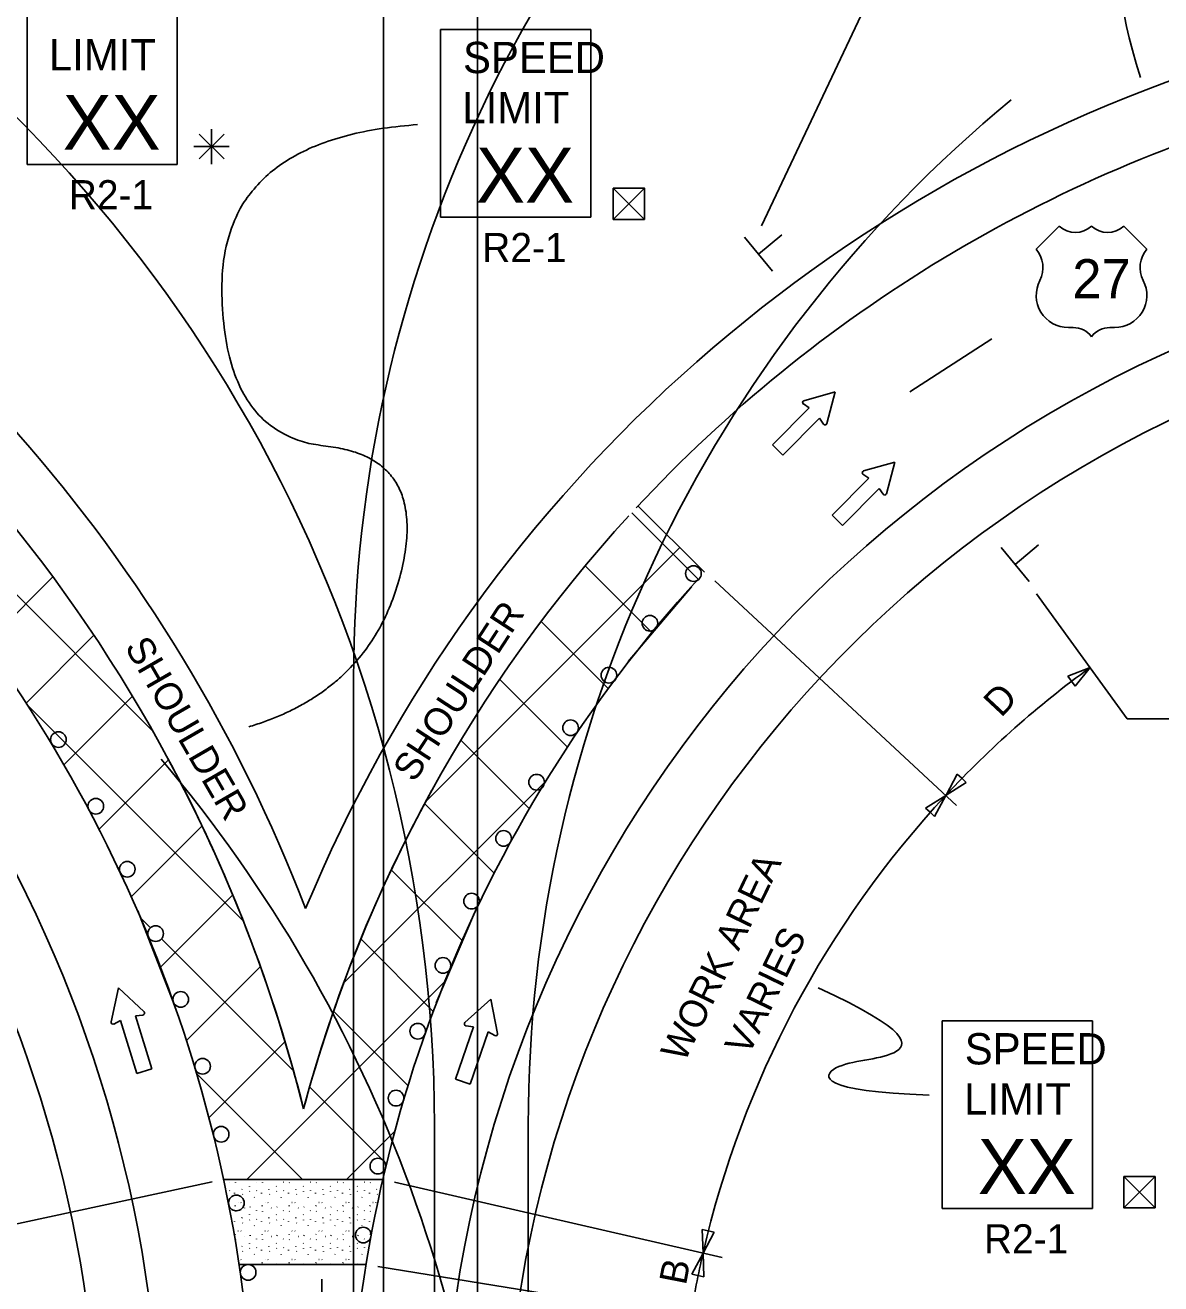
# Model space of a CAD drawing. Extents: x 16728 to 19508, y 5553 to 7079.
# Drawn here: x 16889.1 to 17179.3, y 6484.5 to 6806.3 of the extents above; entities that cross this region are included whole.
import ezdxf

# ---------------------------------------------------------------- set-up
doc = ezdxf.new("R2010")
doc.units = 0
for name, color, linetype in [('ALI_LEGAL_EX', 7, 'Continuous'), ('MT_SCRATCH_LEVEL_A', 7, 'Continuous'), ('MT_SCRATCH_LEVEL_E', 7, 'Continuous'), ('PAVT_EDGE_EX', 7, 'Continuous'), ('TRAFFIC_SIGNS_PR', 7, 'Continuous'), ('TYPICAL_EX', 7, 'Continuous'), ('TYPICAL_TEXT_DIMEN_PR', 7, 'Continuous')]:
    doc.layers.add(name, color=color, linetype=linetype)

msp = doc.modelspace()

# ---------------------------------------------------------------- linework, layer by layer
at = {"layer": 'ALI_LEGAL_EX'}
for p, q in [((16980.68, 6974.12), (16980.68, 6155.98)), ((17004.68, 6974.12), (17004.68, 6155.98)), ((16980.68, 6877.04), (16980.68, 6013.12)), ((17004.68, 6877.04), (17004.68, 6013.12)), ((16973.01, 6139.03), (16973.01, 6639.38)), ((16993.65, 6024.8), (16993.65, 6525.15)), ((17017.65, 6024.8), (17017.65, 6525.15))]:
    msp.add_line(p, q, dxfattribs=at)
for points in [[(17115.18, 6712.56), (17136.15, 6726.16)], [(17043.22, 6643.6), (17059.35, 6662.7)], [(16926.92, 6556.59), (16917.84, 6579.89)], [(16994.08, 6556.37), (17003.86, 6579.38)]]:
    msp.add_lwpolyline(points, dxfattribs=at)
for centre, radius, start, end in [((17313.01, 6639.38), 340, 129.5666, 180), ((16629.65, 6525.15), 364, 0, 57.2958), ((17357.65, 6525.15), 340, 129.5666, 180), ((16583.82, 6435.06), 364, 0, 40.1909), ((17311.82, 6435.06), 340, 137.516, 180), ((16645.75, 6383.76), 364, 0, 40.1909)]:
    msp.add_arc(centre, radius, start, end, dxfattribs=at)
at = {"layer": 'MT_SCRATCH_LEVEL_A'}
for p, q in [((17061.07, 6664.68), (17044.08, 6681.66)), ((17062.67, 6666.45), (17045.68, 6683.43)), ((16921.62, 6625.93), (16870.81, 6676.74)), ((16991.45, 6607.86), (17056.26, 6672.67)), ((17049.24, 6651.05), (17032.19, 6668.09)), ((16878.96, 6648.1), (16896.13, 6665.28)), ((17038.09, 6636.74), (17020.94, 6653.89)), ((16889.3, 6632.99), (16906.63, 6650.32)), ((17027.64, 6621.73), (17010.34, 6639.03)), ((16944.81, 6577.29), (16889.65, 6632.44)), ((16898.97, 6617.2), (16916.49, 6634.73)), ((17017.92, 6606), (17000.4, 6623.52)), ((16907.94, 6600.72), (16925.71, 6618.49)), ((16970.45, 6561.4), (17022.19, 6613.14)), ((17008.93, 6589.53), (16991.15, 6607.31)), ((16916.17, 6583.5), (16934.26, 6601.59)), ((17000.73, 6572.27), (16982.62, 6590.39)), ((16923.64, 6565.51), (16942.1, 6583.97)), ((16921.08, 6575.56), (16918.53, 6578.11)), ((16957.63, 6539.01), (16923.9, 6572.73)), ((16993.37, 6554.18), (16974.85, 6572.7)), ((16930.28, 6546.69), (16949.19, 6565.61)), ((16945.7, 6511.2), (16996.34, 6561.84)), ((16986.9, 6535.2), (16967.87, 6554.22)), ((16936.02, 6526.98), (16955.48, 6546.44)), ((16959.98, 6511.2), (16932.86, 6538.32)), ((16981.44, 6515.19), (16961.77, 6534.87)), ((16971.15, 6511.2), (16983.54, 6523.59)), ((16939.76, 6511.2), (16980.45, 6511.2)), ((16939.76, 6511.2), (16980.45, 6511.2)), ((16980.45, 6511.2), (16939.76, 6511.2)), ((16941.26, 6510.55), (16941.31, 6510.47)), ((16942.79, 6510.41), (16942.84, 6510.33)), ((16945.1, 6511.2), (16945.13, 6511.15)), ((16948.15, 6510.55), (16948.2, 6510.47)), ((16949.68, 6510.41), (16949.73, 6510.33)), ((16951.99, 6511.2), (16952.02, 6511.15)), ((16955.04, 6510.55), (16955.09, 6510.47)), ((16956.57, 6510.41), (16956.62, 6510.33)), ((16958.88, 6511.2), (16958.91, 6511.15)), ((16961.92, 6510.55), (16961.97, 6510.47)), ((16963.45, 6510.41), (16963.51, 6510.33)), ((16965.76, 6511.2), (16965.8, 6511.15)), ((16968.81, 6510.55), (16968.86, 6510.47)), ((16970.34, 6510.41), (16970.39, 6510.33)), ((16972.65, 6511.2), (16972.68, 6511.15)), ((16975.7, 6510.55), (16975.75, 6510.47)), ((16977.23, 6510.41), (16977.28, 6510.33)), ((16979.54, 6511.2), (16979.57, 6511.15)), ((16940.69, 6506.59), (16940.74, 6506.71)), ((16941.31, 6508.34), (16941.36, 6508.27)), ((16942.59, 6507.77), (16942.6, 6507.65)), ((16944.43, 6508.62), (16944.48, 6508.74)), ((16944.62, 6507.42), (16944.67, 6507.35)), ((16946.36, 6509.49), (16946.41, 6509.41)), ((16946.4, 6508.09), (16946.45, 6508.21)), ((16947.58, 6506.59), (16947.63, 6506.71)), ((16948.2, 6508.34), (16948.25, 6508.27)), ((16949.48, 6507.77), (16949.49, 6507.65)), ((16951.32, 6508.62), (16951.37, 6508.74)), ((16951.51, 6507.42), (16951.56, 6507.35)), ((16953.25, 6509.49), (16953.3, 6509.41)), ((16953.29, 6508.09), (16953.34, 6508.21)), ((16954.47, 6506.59), (16954.52, 6506.71)), ((16955.08, 6508.34), (16955.14, 6508.27)), ((16956.37, 6507.77), (16956.38, 6507.65)), ((16958.21, 6508.62), (16958.26, 6508.74)), ((16958.4, 6507.42), (16958.45, 6507.35)), ((16960.13, 6509.49), (16960.19, 6509.41)), ((16960.18, 6508.09), (16960.23, 6508.21)), ((16961.35, 6506.59), (16961.41, 6506.71)), ((16961.97, 6508.34), (16962.02, 6508.27)), ((16963.25, 6507.77), (16963.27, 6507.65)), ((16965.1, 6508.62), (16965.15, 6508.74)), ((16965.28, 6507.42), (16965.33, 6507.35)), ((16967.02, 6509.49), (16967.07, 6509.41)), ((16967.06, 6508.09), (16967.12, 6508.21)), ((16968.24, 6506.59), (16968.29, 6506.71)), ((16968.86, 6508.34), (16968.91, 6508.27)), ((16970.14, 6507.77), (16970.15, 6507.65)), ((16971.98, 6508.62), (16972.03, 6508.74)), ((16972.17, 6507.42), (16972.22, 6507.35)), ((16973.91, 6509.49), (16973.96, 6509.41)), ((16973.95, 6508.09), (16974, 6508.21)), ((16975.13, 6506.59), (16975.18, 6506.71)), ((16975.75, 6508.34), (16975.8, 6508.27)), ((16977.03, 6507.77), (16977.04, 6507.65)), ((16978.87, 6508.62), (16978.92, 6508.74)), ((16979.06, 6507.42), (16979.11, 6507.35)), ((16942.71, 6504.39), (16942.76, 6504.51)), ((16943.47, 6505.35), (16943.53, 6505.28)), ((16944.21, 6505.32), (16944.26, 6505.25)), ((16945.08, 6503.94), (16945.13, 6503.87)), ((16946.53, 6504.1), (16946.58, 6504.21)), ((16949.6, 6504.39), (16949.65, 6504.51)), ((16950.36, 6505.35), (16950.41, 6505.28)), ((16951.1, 6505.32), (16951.15, 6505.25)), ((16951.97, 6503.94), (16952.02, 6503.87)), ((16953.42, 6504.1), (16953.47, 6504.21)), ((16956.49, 6504.39), (16956.54, 6504.51)), ((16957.25, 6505.35), (16957.3, 6505.28)), ((16957.99, 6505.32), (16958.04, 6505.25)), ((16958.86, 6503.94), (16958.91, 6503.87)), ((16960.31, 6504.1), (16960.36, 6504.21)), ((16963.37, 6504.39), (16963.42, 6504.51)), ((16964.14, 6505.35), (16964.19, 6505.28)), ((16964.88, 6505.32), (16964.93, 6505.25)), ((16965.74, 6503.94), (16965.8, 6503.87)), ((16967.19, 6504.1), (16967.24, 6504.21)), ((16970.26, 6504.39), (16970.31, 6504.51)), ((16971.03, 6505.35), (16971.08, 6505.28)), ((16971.76, 6505.32), (16971.81, 6505.25)), ((16972.63, 6503.94), (16972.68, 6503.87)), ((16974.08, 6504.1), (16974.13, 6504.21)), ((16977.15, 6504.39), (16977.2, 6504.51)), ((16977.91, 6505.35), (16977.96, 6505.28)), ((16978.65, 6505.32), (16978.7, 6505.25)), ((16942.59, 6500.48), (16942.6, 6500.37)), ((16942.79, 6503.13), (16942.84, 6503.05)), ((16944.43, 6501.34), (16944.48, 6501.45)), ((16946.36, 6502.21), (16946.41, 6502.13)), ((16946.4, 6500.81), (16946.45, 6500.92)), ((16948.15, 6503.27), (16948.2, 6503.19)), ((16948.2, 6501.06), (16948.25, 6500.98)), ((16949.48, 6500.48), (16949.49, 6500.37)), ((16949.68, 6503.13), (16949.73, 6503.05)), ((16951.32, 6501.34), (16951.37, 6501.45)), ((16953.25, 6502.21), (16953.3, 6502.13)), ((16953.29, 6500.81), (16953.34, 6500.92)), ((16955.04, 6503.27), (16955.09, 6503.19)), ((16955.08, 6501.06), (16955.14, 6500.98)), ((16956.37, 6500.48), (16956.38, 6500.37)), ((16956.57, 6503.13), (16956.62, 6503.05)), ((16958.21, 6501.34), (16958.26, 6501.45)), ((16960.13, 6502.21), (16960.19, 6502.13)), ((16960.18, 6500.81), (16960.23, 6500.92)), ((16961.92, 6503.27), (16961.97, 6503.19)), ((16961.97, 6501.06), (16962.02, 6500.98)), ((16963.25, 6500.48), (16963.27, 6500.37)), ((16963.45, 6503.13), (16963.51, 6503.05)), ((16965.1, 6501.34), (16965.15, 6501.45)), ((16967.02, 6502.21), (16967.07, 6502.13)), ((16967.06, 6500.81), (16967.12, 6500.92)), ((16968.81, 6503.27), (16968.86, 6503.19)), ((16968.86, 6501.06), (16968.91, 6500.98)), ((16970.14, 6500.48), (16970.15, 6500.37)), ((16970.34, 6503.13), (16970.39, 6503.05)), ((16971.98, 6501.34), (16972.03, 6501.45)), ((16973.91, 6502.21), (16973.96, 6502.13)), ((16973.95, 6500.81), (16974, 6500.92)), ((16975.7, 6503.27), (16975.75, 6503.19)), ((16975.75, 6501.06), (16975.8, 6500.98)), ((16977.03, 6500.48), (16977.04, 6500.37)), ((16977.23, 6503.13), (16977.28, 6503.05)), ((16942.71, 6497.11), (16942.76, 6497.23)), ((16943.47, 6498.07), (16943.53, 6497.99)), ((16944.21, 6498.04), (16944.26, 6497.96)), ((16944.62, 6500.14), (16944.67, 6500.06)), ((16947.58, 6499.31), (16947.63, 6499.42)), ((16949.6, 6497.11), (16949.65, 6497.23)), ((16950.36, 6498.07), (16950.41, 6497.99)), ((16951.1, 6498.04), (16951.15, 6497.96)), ((16951.51, 6500.14), (16951.56, 6500.06)), ((16954.47, 6499.31), (16954.52, 6499.42)), ((16956.49, 6497.11), (16956.54, 6497.23)), ((16957.25, 6498.07), (16957.3, 6497.99)), ((16957.99, 6498.04), (16958.04, 6497.96)), ((16958.4, 6500.14), (16958.45, 6500.06)), ((16961.35, 6499.31), (16961.41, 6499.42)), ((16963.37, 6497.11), (16963.42, 6497.23)), ((16964.14, 6498.07), (16964.19, 6497.99)), ((16964.88, 6498.04), (16964.93, 6497.96)), ((16965.28, 6500.14), (16965.33, 6500.06)), ((16968.24, 6499.31), (16968.29, 6499.42)), ((16970.26, 6497.11), (16970.31, 6497.23)), ((16971.03, 6498.07), (16971.08, 6497.99)), ((16971.76, 6498.04), (16971.81, 6497.96)), ((16972.17, 6500.14), (16972.22, 6500.06)), ((16975.13, 6499.31), (16975.18, 6499.42)), ((16977.15, 6497.11), (16977.2, 6497.23)), ((16942.79, 6495.84), (16942.84, 6495.77)), ((16944.43, 6494.05), (16944.48, 6494.17)), ((16945.08, 6496.66), (16945.13, 6496.58)), ((16946.36, 6494.92), (16946.41, 6494.85)), ((16946.53, 6496.81), (16946.58, 6496.93)), ((16948.15, 6495.98), (16948.2, 6495.9)), ((16949.68, 6495.84), (16949.73, 6495.77)), ((16951.32, 6494.05), (16951.37, 6494.17)), ((16951.97, 6496.66), (16952.02, 6496.58)), ((16953.25, 6494.92), (16953.3, 6494.85)), ((16953.42, 6496.81), (16953.47, 6496.93)), ((16955.04, 6495.98), (16955.09, 6495.9)), ((16956.57, 6495.84), (16956.62, 6495.77)), ((16958.21, 6494.05), (16958.26, 6494.17)), ((16958.86, 6496.66), (16958.91, 6496.58)), ((16960.13, 6494.92), (16960.19, 6494.85)), ((16960.31, 6496.81), (16960.36, 6496.93)), ((16961.92, 6495.98), (16961.97, 6495.9)), ((16963.45, 6495.84), (16963.51, 6495.77)), ((16965.1, 6494.05), (16965.15, 6494.17)), ((16965.74, 6496.66), (16965.8, 6496.58)), ((16967.02, 6494.92), (16967.07, 6494.85)), ((16967.19, 6496.81), (16967.24, 6496.93)), ((16968.81, 6495.98), (16968.86, 6495.9)), ((16970.34, 6495.84), (16970.39, 6495.77)), ((16971.98, 6494.05), (16972.03, 6494.17)), ((16972.63, 6496.66), (16972.68, 6496.58)), ((16973.91, 6494.92), (16973.96, 6494.85)), ((16974.08, 6496.81), (16974.13, 6496.93)), ((16975.7, 6495.98), (16975.75, 6495.9)), ((16977.23, 6495.84), (16977.28, 6495.77)), ((16943.53, 6490.71), (16943.53, 6490.71)), ((16944.21, 6490.75), (16944.26, 6490.68)), ((16944.62, 6492.85), (16944.67, 6492.78)), ((16946.4, 6493.52), (16946.45, 6493.64)), ((16947.58, 6492.02), (16947.63, 6492.14)), ((16948.2, 6493.77), (16948.25, 6493.7)), ((16949.48, 6493.2), (16949.49, 6493.08)), ((16950.36, 6490.78), (16950.41, 6490.71)), ((16951.1, 6490.75), (16951.15, 6490.68)), ((16951.51, 6492.85), (16951.56, 6492.78)), ((16953.29, 6493.52), (16953.34, 6493.64)), ((16954.47, 6492.02), (16954.52, 6492.14)), ((16955.08, 6493.77), (16955.14, 6493.7)), ((16956.37, 6493.2), (16956.38, 6493.08)), ((16957.25, 6490.78), (16957.3, 6490.71)), ((16957.99, 6490.75), (16958.04, 6490.68)), ((16958.4, 6492.85), (16958.45, 6492.78)), ((16960.18, 6493.52), (16960.23, 6493.64)), ((16961.35, 6492.02), (16961.41, 6492.14)), ((16961.97, 6493.77), (16962.02, 6493.7)), ((16963.25, 6493.2), (16963.27, 6493.08)), ((16964.14, 6490.78), (16964.19, 6490.71)), ((16964.88, 6490.75), (16964.93, 6490.68)), ((16965.28, 6492.85), (16965.33, 6492.78)), ((16967.06, 6493.52), (16967.12, 6493.64)), ((16968.24, 6492.02), (16968.29, 6492.14)), ((16968.86, 6493.77), (16968.91, 6493.7)), ((16970.14, 6493.2), (16970.15, 6493.08)), ((16971.03, 6490.78), (16971.08, 6490.71)), ((16971.76, 6490.75), (16971.81, 6490.68)), ((16972.17, 6492.85), (16972.22, 6492.78)), ((16973.95, 6493.52), (16974, 6493.64)), ((16975.13, 6492.02), (16975.18, 6492.14)), ((16975.75, 6493.77), (16975.8, 6493.7)), ((16943.73, 6489.46), (16976.2, 6489.46)), ((16943.73, 6489.46), (16976.2, 6489.46)), ((16946.53, 6489.53), (16946.58, 6489.64)), ((16949.6, 6489.82), (16949.65, 6489.94)), ((16953.42, 6489.53), (16953.47, 6489.64)), ((16956.49, 6489.82), (16956.54, 6489.94)), ((16960.31, 6489.53), (16960.36, 6489.64)), ((16963.37, 6489.82), (16963.42, 6489.94)), ((16967.19, 6489.53), (16967.24, 6489.64)), ((16970.26, 6489.82), (16970.31, 6489.94)), ((16974.08, 6489.53), (16974.13, 6489.64))]:
    msp.add_line(p, q, dxfattribs=at)
for centre, radius, start, end in [((16583.82, 6435.06), 388, 14.0483, 28.2673), ((16583.82, 6435.06), 388, 14.0483, 28.2673), ((17311.82, 6435.06), 364, 151.1372, 165.0045), ((17311.82, 6435.06), 364, 151.1372, 165.0044)]:
    msp.add_arc(centre, radius, start, end, dxfattribs=at)
at = {"layer": 'MT_SCRATCH_LEVEL_E'}
for p, q in [((17087.96, 6709.47), (17089.44, 6708.44)), ((17096.12, 6712.53), (17088.1, 6710.29)), ((17093.96, 6704.47), (17096.12, 6712.53)), ((17089.44, 6708.44), (17080.1, 6699.04)), ((17082.75, 6696.4), (17092.1, 6705.8)), ((17092.1, 6705.8), (17093.14, 6704.32)), ((17080.1, 6699.04), (17082.75, 6696.4)), ((17111.35, 6694.57), (17103.33, 6692.34)), ((17109.19, 6686.52), (17111.35, 6694.57)), ((17104.67, 6690.48), (17095.33, 6681.08)), ((17103.19, 6691.51), (17104.67, 6690.48)), ((17097.98, 6678.44), (17107.33, 6687.84)), ((17107.33, 6687.84), (17108.37, 6686.37)), ((17095.33, 6681.08), (17097.98, 6678.44))]:
    msp.add_line(p, q, dxfattribs=at)
for centre, start, end in [((17088.23, 6709.84), 105.5821, 235.121), ((17093.51, 6704.6), 215.1934, 344.9303), ((17103.46, 6691.89), 105.5821, 235.121), ((17108.74, 6686.64), 215.1934, 344.9303)]:
    msp.add_arc(centre, 0.463, start, end, dxfattribs=at)
at = {"layer": 'PAVT_EDGE_EX'}
for centre, radius, start, end in [((17311.82, 6435.06), 380, 105.2177, 157.5011), ((16583.82, 6435.06), 404, 21.0961, 61.4862), ((17311.82, 6435.06), 364, 105.2176, 137.0843), ((16583.82, 6435.06), 388, 14.0482, 61.4862), ((17311.82, 6435.06), 316, 105.2177, 180), ((16583.82, 6435.06), 340, 0, 61.4862), ((17311.82, 6435.06), 300, 105.2177, 180), ((16583.82, 6435.06), 324, 0, 61.4862), ((17311.82, 6435.06), 364, 137.516, 165.0045)]:
    msp.add_arc(centre, radius, start, end, dxfattribs=at)
at = {"layer": 'TRAFFIC_SIGNS_PR'}
for p, q in [((16889.53, 6770.69), (16889.53, 6818.69)), ((16927.92, 6770.69), (16927.92, 6818.69)), ((16995.2, 6805.19), (17033.6, 6805.19)), ((16995.2, 6757.19), (16995.2, 6805.19)), ((17033.6, 6757.19), (17033.6, 6805.19)), ((16889.53, 6770.69), (16927.92, 6770.69)), ((16995.2, 6757.19), (17033.6, 6757.19)), ((17123.44, 6551.75), (17161.84, 6551.75)), ((17123.44, 6503.75), (17123.44, 6551.75)), ((17161.84, 6503.75), (17161.84, 6551.75)), ((17123.44, 6503.75), (17161.84, 6503.75))]:
    msp.add_line(p, q, dxfattribs=at)
for centre in [(17059.87, 6666.11), (17048.74, 6653.41), (17038.25, 6640.13), (17028.46, 6626.68), (16897.56, 6623.67), (17019.79, 6612.77), (16907.11, 6606.63), (17011.34, 6598.39), (16915.15, 6590.52), (17003.16, 6582.36), (16922.4, 6574.05), (16995.84, 6565.92), (16928.82, 6557.24), (16989.4, 6549.11), (16934.41, 6540.13), (16983.84, 6531.99), (16939.15, 6522.76), (16979.2, 6514.61), (16943.03, 6505.19), (16975.47, 6497), (16946.05, 6487.45), (16946.05, 6487.45), (16946.05, 6487.45)]:
    msp.add_circle(centre, 2, dxfattribs=at)
at = {"layer": 'TYPICAL_EX'}
for p, q in [((17147.46, 6749.07), (17153.35, 6754.96)), ((17175.76, 6749.07), (17169.86, 6754.96)), ((17155.7, 6729.01), (17156.88, 6729.01)), ((17167.51, 6729.01), (17166.33, 6729.01))]:
    msp.add_line(p, q, dxfattribs=at)
for centre, radius, start, end in [((17157.48, 6759.26), 5.96, 226.1404, 313.8596), ((17165.73, 6759.26), 5.96, 226.1404, 313.8596), ((17141.87, 6744.35), 7.31, 333.0977, 40.1936), ((17181.34, 6744.35), 7.31, 139.8064, 206.9023), ((17155.72, 6737.25), 8.24, 152.6698, 269.9013), ((17167.5, 6737.25), 8.24, 270.0987, 27.3302), ((17156.9, 6723.1), 5.91, 37.1038, 90.1385), ((17166.32, 6723.1), 5.91, 89.8615, 142.8962)]:
    msp.add_arc(centre, radius, start, end, dxfattribs=at)
at = {"layer": 'TYPICAL_TEXT_DIMEN_PR'}
for p, q in [((17077.28, 6754.99), (17105.34, 6814.46)), ((16939.9, 6778.49), (16933.52, 6772.11)), ((16933.53, 6778.49), (16939.9, 6772.11)), ((16936.71, 6775.3), (16936.71, 6779.76)), ((16936.71, 6775.3), (16932.18, 6775.3)), ((16936.71, 6775.3), (16939.9, 6775.3)), ((16936.71, 6775.3), (16941.19, 6775.3)), ((16936.71, 6775.3), (16936.71, 6770.8)), ((17039.35, 6756.67), (17047.35, 6764.67)), ((17039.35, 6764.66), (17047.35, 6756.67)), ((17080.08, 6743.43), (17072.89, 6752.08)), ((17076.48, 6747.76), (17082.47, 6752.73)), ((17145.69, 6664.12), (17138.51, 6672.77)), ((17142.1, 6668.44), (17148.09, 6673.42)), ((17127.11, 6606.79), (17065.3, 6664.26)), ((17170.75, 6628.99), (17147.51, 6660.94)), ((17155.56, 6639.9), (17161.22, 6642.08)), ((17161.22, 6642.08), (17157.41, 6637.36)), ((17156.48, 6638.63), (17155.56, 6639.9)), ((17157.41, 6637.36), (17156.48, 6638.63)), ((17170.75, 6628.99), (17189.02, 6628.99)), ((17124.44, 6609.48), (17127.28, 6614.84)), ((17127.28, 6614.84), (17128.43, 6613.77)), ((17128.43, 6613.77), (17129.58, 6612.7)), ((17129.58, 6612.7), (17124.44, 6609.48)), ((17119.19, 6606.15), (17124.33, 6609.37)), ((17124.33, 6609.37), (17121.49, 6604.01)), ((17120.34, 6605.08), (17119.19, 6606.15)), ((17121.49, 6604.01), (17120.34, 6605.08)), ((16912.94, 6560.16), (16911.03, 6551.49)), ((16919.44, 6554.09), (16912.94, 6560.16)), ((17008.1, 6557.26), (17001.45, 6551.37)), ((17009.79, 6548.52), (17008.1, 6557.26)), ((16911.74, 6550.94), (16913.45, 6551.82)), ((16913.45, 6551.82), (16917.63, 6538.31)), ((16917.26, 6553), (16919.17, 6553.24)), ((16921.44, 6539.49), (16917.26, 6553)), ((17003.61, 6550.22), (16999.03, 6536.84)), ((17001.7, 6550.52), (17003.61, 6550.22)), ((17002.81, 6535.55), (17007.38, 6548.93)), ((17007.38, 6548.93), (17009.07, 6548)), ((16917.63, 6538.31), (16921.44, 6539.49)), ((16999.03, 6536.84), (17002.81, 6535.55)), ((16852.73, 6492.58), (16936.83, 6510.57)), ((17067.19, 6491.27), (16983.42, 6510.52)), ((17169.85, 6503.95), (17177.85, 6511.95)), ((17169.85, 6511.94), (17177.85, 6503.95)), ((17062.32, 6492.39), (17062.1, 6498.45)), ((17062.1, 6498.45), (17063.63, 6498.1)), ((17065.16, 6497.75), (17062.32, 6492.39)), ((17063.63, 6498.1), (17065.16, 6497.75)), ((17059.47, 6487.03), (17062.32, 6492.39)), ((17062.32, 6492.39), (17062.54, 6486.32)), ((17064.05, 6475.22), (16979.21, 6488.97)), ((16964.92, 6477.95), (16964.92, 6485.73)), ((17061.01, 6486.67), (17059.47, 6487.03)), ((17062.54, 6486.32), (17061.01, 6486.67))]:
    msp.add_line(p, q, dxfattribs=at)
for points in [[(17039.35, 6764.66), (17039.35, 6756.67), (17047.35, 6756.67), (17047.35, 6764.67)], [(17169.85, 6511.94), (17169.85, 6503.95), (17177.85, 6503.95), (17177.85, 6511.95)]]:
    msp.add_lwpolyline(points, close=True, dxfattribs=at)
for centre, radius, start, end in [((17311.82, 6435.06), 256, 126.0328, 137.0506), ((17311.82, 6435.06), 256, 137.0843, 167.0592), ((16919.1, 6553.73), 0.494, 277.2371, 46.974), ((16911.52, 6551.39), 0.494, 167.6257, 297.1647), ((17001.79, 6551), 0.494, 131.5642, 261.1032), ((17009.3, 6548.44), 0.494, 241.1755, 10.9125), ((17311.82, 6435.06), 256, 167.0592, 170.7929)]:
    msp.add_arc(centre, radius, start, end, dxfattribs=at)
for points, degree in [([(17174.09, 6792.93), (17168.08, 6812.93), (17166.4, 6831.03), (17192.21, 6827.78), (17198.29, 6827.27)], 3), ([(16946.2, 6626.92), (16977.56, 6636.36), (16992.5, 6695.83), (16939.3, 6701.55), (16939.4, 6777.31), (16989.33, 6780.91)], 2), ([(17091.76, 6560.17), (17115.63, 6549.26), (17114.31, 6541.73), (17092.95, 6541.73), (17092.08, 6533.65), (17120.14, 6532.79)], 3)]:
    msp.add_open_spline(points, degree=degree, dxfattribs=at)

# ---------------------------------------------------------------- texts
at = {"layer": 'TRAFFIC_SIGNS_PR'}
for s, height, p in [('LIMIT', 8, (16895.13, 6794.75)), ('SPEED', 8, (17000.97, 6794.05)), ('XX', 14.031, (16898.64, 6774.45)), ('LIMIT', 8, (17000.8, 6781.25)), ('XX', 14.031, (17004.31, 6760.95)), ('R2-1', 7.44, (16900.2, 6759.25)), ('R2-1', 7.44, (17005.88, 6745.75)), ('SPEED', 8, (17129.21, 6540.61)), ('LIMIT', 8, (17129.05, 6527.81)), ('XX', 14.031, (17132.55, 6507.51)), ('R2-1', 7.44, (17134.12, 6492.31))]:
    msp.add_text(s, height=height, dxfattribs=at).set_placement(p)
at = {"layer": 'TYPICAL_EX'}
msp.add_text('27', height=10, dxfattribs=at).set_placement((17156.72, 6736.49))
at = {"layer": 'TYPICAL_TEXT_DIMEN_PR'}
for s, rotation, p in [('SHOULDER', 56.8597, (16988.5, 6612.45)), ('SHOULDER', 300.0663, (16914.35, 6647.37)), ('D', 46.9245, (17138.51, 6629.09)), ('WORK AREA', 64.0878, (17057.53, 6540.87)), ('VARIES', 64.0878, (17073.9, 6542.53)), ('B', 78.9226, (17057.92, 6483.97))]:
    msp.add_text(s, height=7, rotation=rotation, dxfattribs=at).set_placement(p)

doc.saveas('drawing.dxf')
